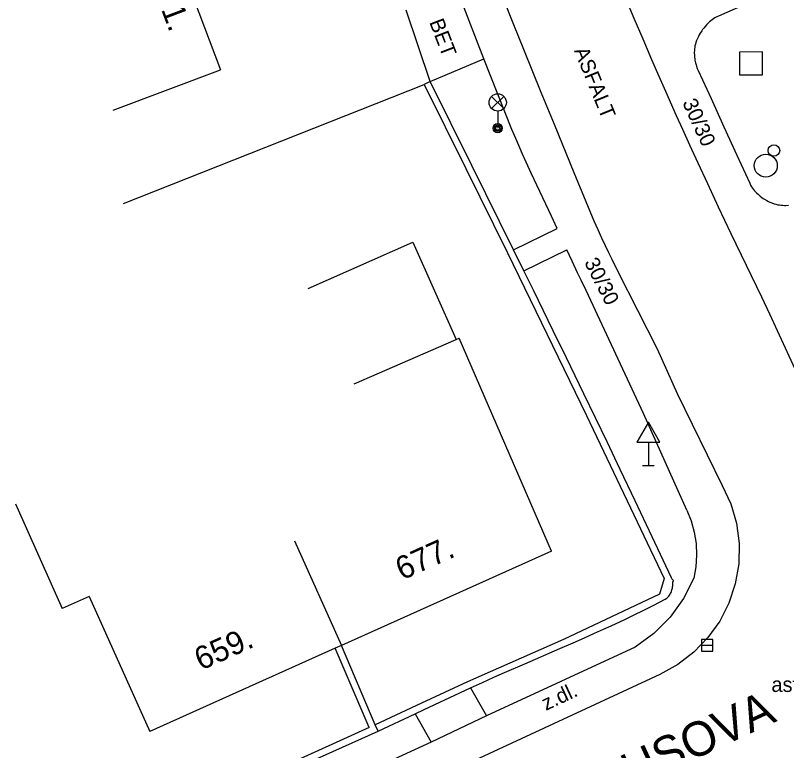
# Model space of a CAD drawing. Extents: x -539515 to -538098, y -1182060 to -1180157.
# Drawn here: x -538312.81 to -538279.17, y -1181253.67 to -1181221.62 of the extents above; entities that cross this region are included whole.
import ezdxf

# ---------------------------------------------------------------- set-up
doc = ezdxf.new("R2010")
doc.units = 0
for name, color, linetype in [('Vrstva 1', 7, 'Continuous'), ('Vrstva 11', 7, 'Continuous'), ('Vrstva 13', 7, 'Continuous'), ('Vrstva 26', 7, 'Continuous'), ('Vrstva 27', 7, 'Continuous'), ('Vrstva 28', 7, 'Continuous'), ('Vrstva 33', 7, 'Continuous'), ('Vrstva 34', 7, 'Continuous'), ('Vrstva 40', 7, 'Continuous'), ('Vrstva 47', 7, 'Continuous'), ('Vrstva 49', 7, 'Continuous'), ('Vrstva 68', 7, 'Continuous'), ('Vrstva 88', 7, 'Continuous')]:
    doc.layers.add(name, color=color, linetype=linetype)

msp = doc.modelspace()

# ---------------------------------------------------------------- linework, layer by layer
at = {"layer": 'Vrstva 1'}
for p, q in [((-538305.279, -1181220.237), (-538303.86, -1181223.99)), ((-538308.537, -1181225.758), (-538303.86, -1181223.99)), ((-538300.041, -1181233.526), (-538295.47, -1181231.5)), ((-538295.47, -1181231.5), (-538293.587, -1181235.749)), ((-538289.419, -1181244.978), (-538293.45, -1181235.69)), ((-538312.805, -1181242.907), (-538310.76, -1181247.47)), ((-538300.636, -1181244.528), (-538298.59, -1181249.09)), ((-538289.419, -1181244.978), (-538298.59, -1181249.09)), ((-538309.593, -1181246.947), (-538310.76, -1181247.47)), ((-538309.593, -1181246.947), (-538306.95, -1181252.84))]:
    msp.add_line(p, q, dxfattribs=at)
for points in [[(-538298.037, -1181237.681), (-538293.587, -1181235.749)], [(-538293.587, -1181235.749), (-538293.45, -1181235.69)], [(-538298.59, -1181249.09), (-538298.866, -1181249.208)], [(-538298.866, -1181249.208), (-538306.95, -1181252.84)]]:
    msp.add_lwpolyline(points, dxfattribs=at)
at = {"layer": 'Vrstva 11'}
msp.add_line((-538294.71, -1181224.5), (-538295.76, -1181221.39), dxfattribs=at)
at = {"layer": 'Vrstva 13'}
for p, q in [((-538292.38, -1181223.51), (-538293.562, -1181220.456)), ((-538294.71, -1181224.5), (-538292.38, -1181223.51)), ((-538291.08, -1181231.84), (-538289.18, -1181230.91)), ((-538290.632, -1181232.756), (-538288.76, -1181231.84)), ((-538283.53, -1181243.19), (-538285.41, -1181238.97)), ((-538285.78, -1181249.16), (-538292.262, -1181252.151)), ((-538292.96, -1181250.94), (-538292.262, -1181252.151)), ((-538295.367, -1181252.063), (-538294.67, -1181253.3)), ((-538292.262, -1181252.151), (-538294.67, -1181253.3)), ((-538294.67, -1181253.3), (-538301.793, -1181256.552))]:
    msp.add_line(p, q, dxfattribs=at)
for points in [[(-538278.865, -1181220.195), (-538282.14, -1181221.65), (-538282.221, -1181221.689), (-538282.295, -1181221.73), (-538282.362, -1181221.773), (-538282.423, -1181221.816), (-538282.479, -1181221.859), (-538282.53, -1181221.901), (-538282.576, -1181221.943), (-538282.66, -1181222.026), (-538282.729, -1181222.102), (-538282.786, -1181222.172), (-538282.834, -1181222.236), (-538282.874, -1181222.293), (-538282.94, -1181222.396), (-538282.985, -1181222.475), (-538283.017, -1181222.535), (-538283.061, -1181222.627), (-538283.1, -1181222.72), (-538283.128, -1181222.798), (-538283.15, -1181222.872), (-538283.167, -1181222.944), (-538283.179, -1181223.011), (-538283.188, -1181223.075), (-538283.193, -1181223.135), (-538283.198, -1181223.249), (-538283.195, -1181223.349), (-538283.189, -1181223.437), (-538283.179, -1181223.513), (-538283.168, -1181223.579), (-538283.144, -1181223.694), (-538283.121, -1181223.778), (-538283.101, -1181223.84), (-538283.068, -1181223.931), (-538283.03, -1181224.02)], [(-538289.18, -1181230.91), (-538289.428, -1181230.371), (-538290.316, -1181228.492), (-538290.534, -1181228.02), (-538290.694, -1181227.665), (-538290.812, -1181227.398), (-538290.984, -1181226.995), (-538291.15, -1181226.59), (-538291.765, -1181225.05), (-538292.38, -1181223.51)], [(-538283.03, -1181224.02), (-538282.468, -1181225.25), (-538281.905, -1181226.48), (-538281.342, -1181227.71), (-538280.78, -1181228.94), (-538280.741, -1181229.018), (-538280.7, -1181229.088), (-538280.658, -1181229.152), (-538280.615, -1181229.211), (-538280.572, -1181229.264), (-538280.529, -1181229.313), (-538280.487, -1181229.357), (-538280.404, -1181229.435), (-538280.328, -1181229.5), (-538280.258, -1181229.554), (-538280.195, -1181229.598), (-538280.138, -1181229.634), (-538280.037, -1181229.693), (-538279.959, -1181229.733), (-538279.9, -1181229.761), (-538279.81, -1181229.798), (-538279.72, -1181229.83), (-538279.635, -1181229.855), (-538279.554, -1181229.873), (-538279.477, -1181229.886), (-538279.403, -1181229.895), (-538279.334, -1181229.901), (-538279.268, -1181229.903), (-538279.207, -1181229.903), (-538279.09, -1181229.898)], [(-538287.911, -1181233.607), (-538288.129, -1181233.168), (-538288.29, -1181232.838), (-538288.528, -1181232.341), (-538288.76, -1181231.84)], [(-538285.41, -1181238.97), (-538287.911, -1181233.607)], [(-538283.53, -1181243.19), (-538283.336, -1181243.662), (-538283.2, -1181244.148), (-538283.12, -1181244.646), (-538283.097, -1181245.151), (-538283.13, -1181245.654), (-538283.22, -1181246.15)], [(-538283.22, -1181246.15), (-538283.67, -1181247.047), (-538284.256, -1181247.859), (-538284.964, -1181248.569), (-538285.78, -1181249.16)]]:
    msp.add_lwpolyline(points, dxfattribs=at)
at = {"layer": 'Vrstva 26'}
msp.add_lwpolyline([(-538281.226, -1181224.219), (-538280.225, -1181224.218), (-538280.226, -1181223.217), (-538281.227, -1181223.218)], close=True, dxfattribs=at)
at = {"layer": 'Vrstva 27'}
msp.add_line((-538282.89, -1181249.08), (-538282.39, -1181249.08), dxfattribs=at)
msp.add_lwpolyline([(-538282.89, -1181249.33), (-538282.39, -1181249.33), (-538282.39, -1181248.83), (-538282.89, -1181248.83)], close=True, dxfattribs=at)
msp.add_circle((-538280.08, -1181228.17), 0.5, dxfattribs=at)
at = {"layer": 'Vrstva 28'}
msp.add_circle((-538279.724, -1181227.51), 0.25, dxfattribs=at)
at = {"layer": 'Vrstva 33'}
for p, q in [((-538292.035, -1181225.68), (-538291.505, -1181225.15)), ((-538292.035, -1181225.15), (-538291.505, -1181225.68)), ((-538291.77, -1181225.79), (-538291.77, -1181226.54))]:
    msp.add_line(p, q, dxfattribs=at)
for centre, radius in [((-538291.77, -1181225.415), 0.375), ((-538291.77, -1181226.54), 0.2), ((-538291.77, -1181226.54), 0.145), ((-538291.77, -1181226.54), 0.0876)]:
    msp.add_circle(centre, radius, dxfattribs=at)
at = {"layer": 'Vrstva 34'}
for p, q in [((-538285.2, -1181240.224), (-538285.2, -1181241.24)), ((-538285.45, -1181241.24), (-538284.95, -1181241.24))]:
    msp.add_line(p, q, dxfattribs=at)
msp.add_lwpolyline([(-538285.7, -1181240.224), (-538284.7, -1181240.224), (-538285.2, -1181239.356)], close=True, dxfattribs=at)
at = {"layer": 'Vrstva 68'}
for p, q in [((-538308.086, -1181229.817), (-538294.979, -1181224.633)), ((-538291.35, -1181231.972), (-538287.892, -1181239.059)), ((-538287.892, -1181239.059), (-538284.511, -1181246.165)), ((-538297.382, -1181252.668), (-538298.866, -1181249.208)), ((-538297.382, -1181252.668), (-538303.453, -1181255.406))]:
    msp.add_line(p, q, dxfattribs=at)
for points in [[(-538291.08, -1181231.84), (-538292.895, -1181228.17), (-538294.71, -1181224.5), (-538294.979, -1181224.633)], [(-538294.979, -1181224.633), (-538293.164, -1181228.302), (-538291.35, -1181231.972)], [(-538290.632, -1181232.756), (-538291.08, -1181231.84)], [(-538286.429, -1181241.414), (-538287.003, -1181240.214), (-538288.012, -1181238.116), (-538288.774, -1181236.544), (-538289.348, -1181235.366), (-538290.212, -1181233.601), (-538290.632, -1181232.756)], [(-538285.776, -1181242.784), (-538286.429, -1181241.414)], [(-538287.984, -1181248.754), (-538287.544, -1181248.558), (-538287.159, -1181248.384), (-538286.822, -1181248.23), (-538286.233, -1181247.954), (-538285.792, -1181247.742), (-538285.461, -1181247.579), (-538284.965, -1181247.329), (-538284.718, -1181247.2), (-538284.47, -1181247.07), (-538284.394, -1181247.019), (-538284.351, -1181246.981), (-538284.314, -1181246.94), (-538284.282, -1181246.898), (-538284.255, -1181246.857), (-538284.232, -1181246.816), (-538284.212, -1181246.776), (-538284.196, -1181246.737), (-538284.17, -1181246.662), (-538284.153, -1181246.595), (-538284.143, -1181246.535), (-538284.137, -1181246.482), (-538284.134, -1181246.436), (-538284.134, -1181246.397), (-538284.139, -1181246.328), (-538284.11, -1181246.25), (-538284.17, -1181246.19), (-538284.19, -1181246.14), (-538285.033, -1181244.351), (-538285.776, -1181242.784)], [(-538284.511, -1181246.165), (-538284.718, -1181246.853), (-538288.903, -1181248.826)], [(-538296.99, -1181252.82), (-538295.367, -1181252.063), (-538294.975, -1181251.88), (-538292.96, -1181250.94), (-538292.431, -1181250.696), (-538291.935, -1181250.472), (-538291.469, -1181250.266), (-538290.594, -1181249.885), (-538289.062, -1181249.224), (-538288.487, -1181248.974), (-538287.984, -1181248.754)], [(-538296.99, -1181252.82), (-538297.109, -1181252.543), (-538298.59, -1181249.09)], [(-538288.903, -1181248.826), (-538293.086, -1181250.668), (-538295.098, -1181251.606), (-538297.109, -1181252.543)], [(-538302.359, -1181255.242), (-538296.99, -1181252.82)]]:
    msp.add_lwpolyline(points, dxfattribs=at)
at = {"layer": 'Vrstva 88'}
for p, q in [((-538279.9, -1181234.65), (-538280.25, -1181233.91)), ((-538277.33, -1181240.27), (-538279.9, -1181234.65)), ((-538284.7, -1181250.35), (-538300.95, -1181257.88))]:
    msp.add_line(p, q, dxfattribs=at)
for points in [[(-538285.82, -1181221.76), (-538286.372, -1181220.413), (-538286.79, -1181219.401), (-538287.099, -1181218.642), (-538287.329, -1181218.071), (-538287.668, -1181217.212), (-538287.835, -1181216.782), (-538288, -1181216.35), (-538288.59, -1181214.794), (-538289.105, -1181213.433)], [(-538293.08, -1181216.926), (-538292.749, -1181217.784), (-538292.121, -1181219.39), (-538291.566, -1181220.794), (-538291.077, -1181222.02), (-538290.646, -1181223.092), (-538289.886, -1181224.965)], [(-538285.431, -1181222.659), (-538285.82, -1181221.76)], [(-538281.586, -1181231.143), (-538282.136, -1181229.98), (-538282.613, -1181228.96), (-538283.027, -1181228.067), (-538283.386, -1181227.285), (-538283.698, -1181226.599), (-538283.969, -1181225.997), (-538284.439, -1181224.943), (-538284.788, -1181224.15), (-538285.047, -1181223.555), (-538285.431, -1181222.659)], [(-538289.886, -1181224.965), (-538289.311, -1181226.368)], [(-538289.311, -1181226.368), (-538288.444, -1181228.47), (-538287.58, -1181230.57), (-538287.405, -1181230.956), (-538287.244, -1181231.314), (-538287.09, -1181231.648), (-538286.942, -1181231.958), (-538286.801, -1181232.247), (-538286.531, -1181232.787)], [(-538280.25, -1181233.91), (-538281.586, -1181231.143)], [(-538286.531, -1181232.787), (-538284.81, -1181236.15)], [(-538284.81, -1181236.15), (-538283.95, -1181238.11), (-538281.98, -1181242.11)], [(-538281.98, -1181242.11), (-538281.607, -1181242.912), (-538281.361, -1181243.762), (-538281.245, -1181244.639), (-538281.262, -1181245.524), (-538281.41, -1181246.397), (-538281.688, -1181247.237), (-538282.088, -1181248.027), (-538282.602, -1181248.747), (-538283.217, -1181249.383), (-538283.921, -1181249.92), (-538284.7, -1181250.35)]]:
    msp.add_lwpolyline(points, dxfattribs=at)

# ---------------------------------------------------------------- texts
at = {"layer": 'Vrstva 40'}
for s, rotation, p in [('BET', 291.1581, (-538294.766, -1181221.912)), ('ASFALT', 292.27, (-538288.452, -1181223.154)), ('30/30', 294.4686, (-538283.731, -1181225.421)), ('30/30', 297.1509, (-538288.013, -1181232.384)), ('z.dl.', 25.0019, (-538289.67, -1181251.942))]:
    msp.add_text(s, height=0.65, rotation=rotation, dxfattribs=at).set_placement(p)
msp.add_text('asf.', height=0.65, dxfattribs=at).set_placement((-538279.833, -1181251.115))
at = {"layer": 'Vrstva 47'}
for s, rotation, p in [('511.', 290.7115, (-538306.986, -1181219.964)), ('677.', 24.15, (-538295.943, -1181246.259)), ('659.', 24.1593, (-538304.712, -1181250.192))]:
    msp.add_text(s, height=1, rotation=rotation, dxfattribs=at).set_placement(p)
at = {"layer": 'Vrstva 49'}
msp.add_text('ul. HUSOVA', height=1.5, rotation=24.8218, dxfattribs=at).set_placement((-538289.665, -1181257.055))

doc.saveas('drawing.dxf')
